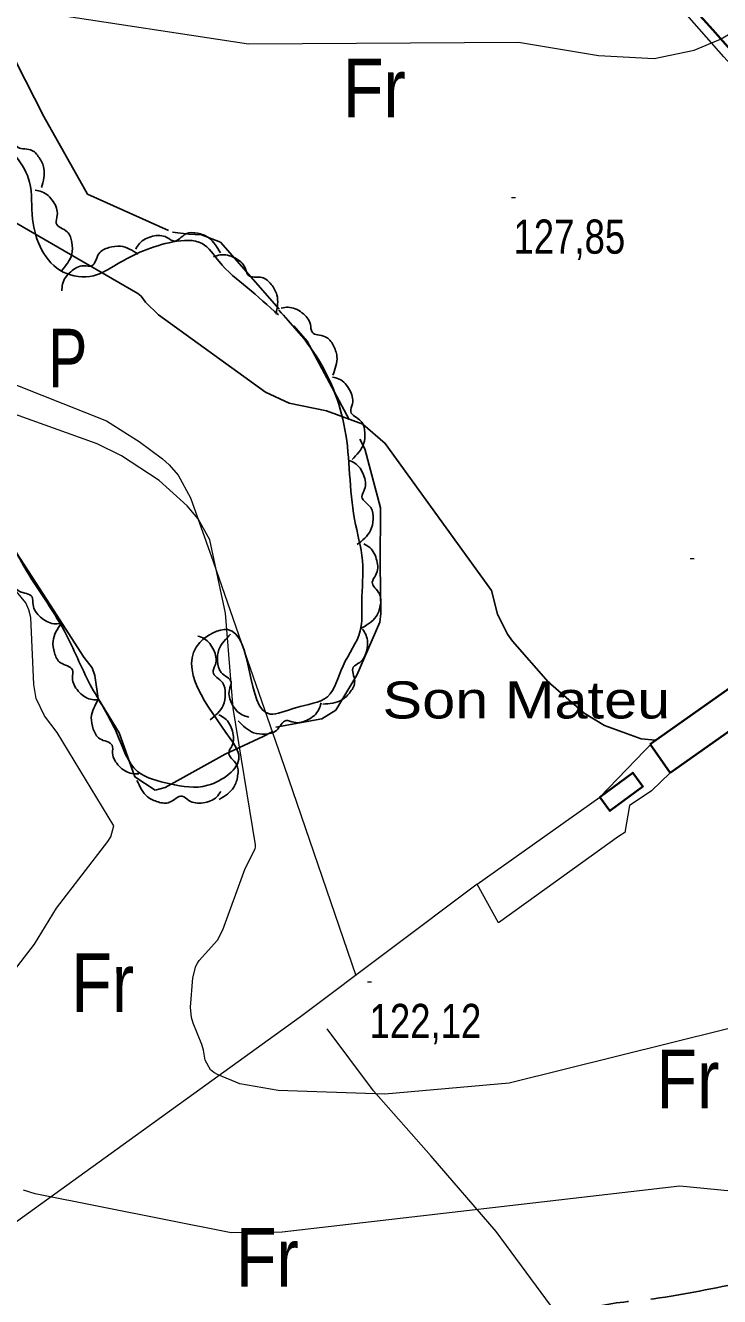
# Model space of a CAD drawing. Extents: x 483847 to 488453, y 4383581 to 4386795.
# Drawn here: x 485756 to 485933.9, y 4384534.4 to 4384859.8 of the extents above; entities that cross this region are included whole.
import ezdxf
from ezdxf.enums import TextEntityAlignment as Align

# ---------------------------------------------------------------- set-up
doc = ezdxf.new("R2010")
doc.units = 0
doc.header["$LTSCALE"] = 3.8
doc.linetypes.add('LONG_DASHED', pattern=[7.5, 6, -1.5])
for name, color, linetype, lineweight in [('25', 7, 'LONG_DASHED', 25), ('27', 7, 'Continuous', 25), ('38', 7, 'Continuous', 25), ('47', 7, 'Continuous', 35), ('51', 7, 'Continuous', 13), ('6', 7, 'Continuous', 35), ('7', 7, 'Continuous', 13), ('8', 7, 'Continuous', 25), ('9', 7, 'Continuous', 13)]:
    doc.layers.add(name, color=color, linetype=linetype, lineweight=lineweight)
doc.layers.add('31', color=7, linetype='Continuous')
doc.layers.add('5', color=7, linetype='Continuous')

msp = doc.modelspace()

# ---------------------------------------------------------------- linework, layer by layer
at = {"layer": '25'}
for points in [[(485737.43, 4384861.64), (485748.45, 4384855.7), (485753.63, 4384850.45), (485760.78, 4384836.54), (485771.9, 4384816.65), (485793.75, 4384806.88), (485797.87, 4384806.37), (485801.17, 4384806.25), (485806.02, 4384804.3), (485828.24, 4384779), (485843, 4384751.47), (485846.99, 4384736.33), (485846.93, 4384721.85), (485847.05, 4384709.24), (485846.79, 4384707.07), (485840.9, 4384693.5), (485835.52, 4384684.5), (485831.96, 4384682.3), (485820.15, 4384680.22)], [(485819.28, 4384679), (485816.96, 4384677.78), (485807.22, 4384673.27), (485791.86, 4384664.71), (485789.3, 4384664.07), (485784.02, 4384667.45), (485780.06, 4384678.76), (485774.63, 4384687.55), (485773.81, 4384693.41), (485773.09, 4384695.37), (485770.95, 4384698.1), (485762.37, 4384711.51), (485748.86, 4384732.34), (485727.51, 4384745.77), (485724.07, 4384746.42), (485717.84, 4384746.21), (485716.04, 4384745.94), (485697.39, 4384732.85), (485694.47, 4384728.16), (485689.48, 4384725.68), (485678.02, 4384742.58), (485665.24, 4384761.82), (485657.95, 4384774.45)]]:
    msp.add_lwpolyline(points, dxfattribs=at)
at = {"layer": '27'}
for points in [[(485820.93, 4384786.91), (485829.93, 4384776.12), (485837.9, 4384756.42), (485840.34, 4384733.43), (485842.37, 4384722.82), (485842.22, 4384712.24), (485841.81, 4384704.82), (485837.4, 4384695.88), (485833.39, 4384687.98), (485825.25, 4384685.17), (485818.69, 4384683.54), (485807.82, 4384705.15), (485800.72, 4384701.88), (485808.47, 4384677.31), (485810.73, 4384672.55), (485802.75, 4384665.31), (485793.07, 4384665.67), (485784.72, 4384668.87), (485779.53, 4384678.4), (485772.65, 4384691.03), (485766.02, 4384704.78), (485755.6, 4384721.43), (485746.57, 4384734.84), (485744.49, 4384736.3), (485736.37, 4384740.47), (485729.51, 4384748.52), (485725.04, 4384751.21), (485714.1, 4384746.79), (485702, 4384740.29), (485696.24, 4384736.32), (485692.16, 4384734.72), (485687.22, 4384735.4), (485671.47, 4384756.41), (485668.54, 4384767.03), (485665.8, 4384774.95), (485670.52, 4384784.41), (485677.36, 4384795.72), (485684.82, 4384813.84), (485690.85, 4384831.69), (485692.85, 4384845.62), (485697.04, 4384854.64), (485705.14, 4384864.95), (485713.55, 4384865.58), (485722.78, 4384860.5), (485736.67, 4384840.26), (485747.95, 4384831.55), (485757.09, 4384819.71), (485757.85, 4384810.25), (485765.69, 4384796.7), (485773.48, 4384795.76), (485779.37, 4384798.61), (485793.86, 4384804.4), (485801.29, 4384804), (485805.65, 4384799.36), (485812.83, 4384792.73), (485820.83, 4384785.71)], [(485745.45, 4384834.26), (485747.18, 4384834.64), (485750.82, 4384833.56), (485753.24, 4384830.77), (485753.86, 4384828.81), (485757.32, 4384827.97), (485759.55, 4384825.99), (485760.77, 4384823.23), (485760.16, 4384818.3)], [(485758.53, 4384817.64), (485760.26, 4384817.26), (485763.12, 4384814.76), (485764.17, 4384811.22), (485763.92, 4384809.18), (485766.71, 4384806.99), (485767.92, 4384804.26), (485767.88, 4384801.23), (485765.28, 4384797.01)], [(485784.29, 4384802.55), (485785.26, 4384804.04), (485788.6, 4384805.84), (485792.28, 4384805.56), (485794.1, 4384804.61), (485797.14, 4384806.45), (485800.12, 4384806.62), (485802.94, 4384805.51), (485805.97, 4384801.59)], [(485765.39, 4384791.85), (485765.53, 4384793.62), (485767.62, 4384796.78), (485770.99, 4384798.29), (485773.05, 4384798.32), (485774.86, 4384801.38), (485777.4, 4384802.94), (485780.4, 4384803.3), (485784.93, 4384801.28)], [(485804.25, 4384800.57), (485805.94, 4384801.09), (485809.66, 4384800.33), (485812.31, 4384797.76), (485813.09, 4384795.86), (485816.61, 4384795.32), (485819, 4384793.54), (485820.45, 4384790.88), (485820.26, 4384785.93)], [(485821.58, 4384787.48), (485823.34, 4384787.69), (485826.87, 4384786.29), (485829.03, 4384783.3), (485829.47, 4384781.29), (485832.83, 4384780.14), (485834.88, 4384777.97), (485835.84, 4384775.1), (485834.79, 4384770.26)], [(485834.71, 4384769.81), (485836.41, 4384769.29), (485839.05, 4384766.57), (485839.8, 4384762.95), (485839.38, 4384760.94), (485841.99, 4384758.52), (485842.97, 4384755.7), (485842.68, 4384752.69), (485839.73, 4384748.7)], [(485838.8, 4384748.53), (485840.41, 4384747.79), (485842.67, 4384744.75), (485842.94, 4384741.07), (485842.26, 4384739.13), (485844.52, 4384736.38), (485845.12, 4384733.46), (485844.44, 4384730.51), (485840.99, 4384726.94)], [(485765.07, 4384706.73), (485763.29, 4384706.66), (485759.9, 4384708.35), (485757.99, 4384711.51), (485757.72, 4384713.55), (485754.46, 4384714.97), (485752.6, 4384717.3), (485751.87, 4384720.24), (485753.32, 4384724.98)], [(485842.73, 4384727.11), (485844.23, 4384726.16), (485846.06, 4384722.83), (485845.82, 4384719.15), (485844.89, 4384717.32), (485846.75, 4384714.29), (485846.95, 4384711.31), (485845.87, 4384708.49), (485841.97, 4384705.42)], [(485774.49, 4384687.17), (485772.72, 4384687.33), (485769.57, 4384689.43), (485768.08, 4384692.81), (485768.06, 4384694.86), (485765.01, 4384696.69), (485763.46, 4384699.24), (485763.11, 4384702.24), (485765.15, 4384706.76)], [(485800.23, 4384703.49), (485801.87, 4384702.83), (485804.27, 4384699.89), (485804.7, 4384696.22), (485804.11, 4384694.25), (485806.49, 4384691.61), (485807.22, 4384688.72), (485806.67, 4384685.75), (485803.39, 4384682.03)], [(485813.23, 4384682.78), (485811.55, 4384683.33), (485808.96, 4384686.1), (485808.28, 4384689.73), (485808.73, 4384691.73), (485806.17, 4384694.2), (485805.24, 4384697.04), (485805.59, 4384700.04), (485808.61, 4384703.98)], [(485842.36, 4384705.27), (485843.29, 4384703.76), (485843.49, 4384699.98), (485841.67, 4384696.76), (485840.03, 4384695.52), (485840.39, 4384691.99), (485839.27, 4384689.22), (485837.07, 4384687.15), (485832.22, 4384686.09)], [(485785.07, 4384668.22), (485783.3, 4384668.28), (485780.04, 4384670.21), (485778.37, 4384673.51), (485778.24, 4384675.56), (485775.1, 4384677.21), (485773.41, 4384679.68), (485772.91, 4384682.66), (485774.71, 4384687.28)], [(485831.76, 4384686.37), (485831.21, 4384684.69), (485828.43, 4384682.1), (485824.8, 4384681.43), (485822.8, 4384681.88), (485820.33, 4384679.33), (485817.49, 4384678.41), (485814.48, 4384678.76), (485810.55, 4384681.79)], [(485805.59, 4384683.33), (485807.12, 4384682.43), (485809.07, 4384679.18), (485808.97, 4384675.48), (485808.12, 4384673.62), (485810.09, 4384670.67), (485810.4, 4384667.7), (485809.43, 4384664.84), (485805.66, 4384661.63)], [(485806.13, 4384663.72), (485805.04, 4384662.32), (485801.55, 4384660.82), (485797.91, 4384661.41), (485796.18, 4384662.52), (485792.98, 4384660.95), (485790, 4384661.04), (485787.29, 4384662.38), (485784.61, 4384666.55)], [(485586.07, 4384404.96), (485597.78, 4384411.17), (485606.35, 4384417.2), (485622.8, 4384434.3), (485638.04, 4384445.26), (485644.5, 4384445.62), (485658.99, 4384445.86), (485668.07, 4384446.18), (485677.83, 4384446.56), (485685.78, 4384446.52), (485686.16, 4384446.52), (485695.75, 4384445.63), (485705.07, 4384446.85), (485720.26, 4384453.83), (485731.69, 4384460.95), (485744.83, 4384466.76), (485753.85, 4384468.21), (485762.1, 4384467.94), (485771.46, 4384466.38), (485779.77, 4384465.21), (485792.44, 4384459.25), (485803.25, 4384459.25), (485830.42, 4384465.39), (485855.97, 4384473.28), (485881.92, 4384482.28), (485908.3, 4384490.54), (485915.32, 4384493.44), (485922.33, 4384495.59), (485931.48, 4384495.68), (485950.13, 4384498.57), (485982.66, 4384501.4), (486018.63, 4384502.69), (486042.78, 4384507.44), (486070.69, 4384512.67), (486104.24, 4384513.09), (486123.28, 4384517.17), (486134.56, 4384518.36), (486141.25, 4384519.31), (486150.43, 4384521.51), (486171.2, 4384525.11), (486181.12, 4384526.7), (486198.83, 4384526.52), (486209.89, 4384528.39), (486216.24, 4384532.2), (486231.76, 4384541.73), (486248.98, 4384549.44), (486261.04, 4384553.17), (486271.06, 4384556.25), (486282.21, 4384558.87), (486287.69, 4384558.94), (486300.96, 4384558.6), (486310.55, 4384557.18), (486316.3, 4384555.23), (486321.69, 4384554.32), (486328.92, 4384556.7), (486335.23, 4384562.38), (486343.66, 4384568.94), (486364.13, 4384578.33), (486366, 4384578), (486368.6, 4384576.09), (486369.79, 4384575.39), (486372.24, 4384574.08), (486374.23, 4384571.43), (486375.15, 4384567.21), (486374.25, 4384561.97), (486372.4, 4384559.07), (486370.63, 4384555.87), (486352.9, 4384543.97), (486339.38, 4384532.31), (486332.19, 4384527.76), (486317.97, 4384520.39), (486311.22, 4384515.38), (486308.88, 4384513.84), (486298.76, 4384488.69), (486287.54, 4384464.54), (486285.75, 4384455.41), (486283.18, 4384443.07), (486279.57, 4384432.24), (486279.26, 4384426.39), (486278.79, 4384419.5), (486290, 4384406.28), (486334.09, 4384403.62), (486358.16, 4384397.5), (486380.73, 4384396.58), (486398.89, 4384396.32), (486406.69, 4384396.05), (486425.56, 4384393.46), (486433.95, 4384392.44), (486444.35, 4384390.71), (486451.38, 4384388.51), (486459.96, 4384385.16)]]:
    msp.add_spline(points, degree=3, dxfattribs=at)
at = {"layer": '38', "linetype": 'LONG_DASHED'}
msp.add_spline([(485450.32, 4384320.61), (485462.4, 4384320.51), (485473.43, 4384320.88), (485482.62, 4384323.37), (485490, 4384324.99), (485501.85, 4384330.15), (485516.14, 4384337.75), (485524.23, 4384341.46), (485529.61, 4384345.21), (485577.96, 4384368.38), (485586, 4384374.12), (485596.57, 4384383.8), (485611.96, 4384394.76), (485621.26, 4384405.35), (485631.35, 4384418.34), (485634.75, 4384424.97), (485637, 4384429.97), (485638.56, 4384434.37), (485640.35, 4384438.77), (485643.85, 4384441.95), (485651.49, 4384446.42), (485654.54, 4384449.45), (485656.6, 4384451.89), (485673.07, 4384454.44), (485675.46, 4384454.03), (485679.49, 4384452.62), (485718.1, 4384455.44), (485729.3, 4384461.58), (485760.12, 4384476.15), (485767.32, 4384476.05), (485770.98, 4384475.09), (485773.52, 4384473.93), (485779.62, 4384470.09), (485800.09, 4384479.48), (485803.29, 4384483.18), (485810.72, 4384488.63), (485821.25, 4384495.76), (485840.3, 4384505.47), (485862.7, 4384518.73), (485872.14, 4384522.34), (485887.66, 4384526.92), (485901.83, 4384531.75), (485917.02, 4384533.86), (485940.42, 4384538.02), (485963.89, 4384541.96), (485980.94, 4384549), (485983.45, 4384550.99), (485984.28, 4384556.38), (485984.82, 4384562.6), (485988.91, 4384576.12), (485990.86, 4384596.58), (485991.2, 4384615.56), (485990.27, 4384628.78), (485985.71, 4384640.7), (485973.12, 4384647.03), (485967.85, 4384650.79), (485962.31, 4384652.22), (485945.83, 4384664.31), (485943.49, 4384668.84), (485940.51, 4384675.64), (485940.42, 4384675.76)], degree=3, dxfattribs=at)
at = {"layer": '47'}
for points in [[(485916.06, 4384675.84), (485941.6, 4384693.82), (485946.75, 4384686.51), (485921.21, 4384668.53)], [(485903.18, 4384662.29), (485911.63, 4384668.53), (485914.25, 4384664.99), (485905.8, 4384658.75)]]:
    msp.add_lwpolyline(points, close=True, dxfattribs=at)
at = {"layer": '51'}
for points in [[(485943.4, 4384693.68), (485995.22, 4384733.68), (486026.99, 4384756.87), (486028.59, 4384758.12), (486029.05, 4384758.71), (486029.82, 4384760.28), (486020.31, 4384767.02), (486005.23, 4384777.66), (485993.83, 4384788.63), (485987.41, 4384795.93), (485978.38, 4384804.91), (485958.28, 4384826.36), (485935.01, 4384851.75), (485913.45, 4384876.3), (485888.7, 4384903.29), (485871.64, 4384922.45), (485863.33, 4384934.27), (485854.19, 4384945.58), (485850, 4384951.95), (485847.79, 4384954.83), (485847.28, 4384955.66), (485846.47, 4384956.72)], [(485748.94, 4384769.63), (485776.77, 4384758.57), (485782.2, 4384755.2), (485785.18, 4384753.28), (485791.12, 4384748.91), (485792.82, 4384747.31), (485795.18, 4384744.73), (485798.33, 4384738.91), (485804.17, 4384722.61), (485822.33, 4384670.2), (485840.66, 4384616.62)], [(485921.21, 4384668.53), (485916.41, 4384663.9), (485915.8, 4384663.46), (485910.8, 4384660.16), (485909.58, 4384653.2), (485907.99, 4384652.17), (485877.21, 4384630.1), (485871.8, 4384640.01), (485903.18, 4384662.29), (485916.98, 4384676.49)], [(485871.8, 4384640.01), (485826.51, 4384605.99), (485743.79, 4384546.47), (485696.68, 4384510.22), (485687.56, 4384502.33)], [(485891.98, 4384530.24), (485876.67, 4384551.09), (485859.99, 4384570.32), (485845.22, 4384587.04), (485833.37, 4384602.96)]]:
    msp.add_lwpolyline(points, dxfattribs=at)
at = {"layer": '6'}
msp.add_lwpolyline([(485848.5, 4384958.28), (485858.98, 4384943.82), (485873.22, 4384924.97), (485884.69, 4384911.41), (485895.78, 4384898.93), (485914.77, 4384877.86), (485932.13, 4384858.72), (485950.08, 4384838.41), (485969.52, 4384818.02), (485987.78, 4384798.02), (486000.62, 4384784.64), (486017.02, 4384770.37), (486029.23, 4384762), (486031.51, 4384760.15)], dxfattribs=at)
at = {"layer": '7'}
for p, q in [((485880.57, 4384815.76), (485881.57, 4384815.76)), ((485926.37, 4384723.33), (485927.37, 4384723.33)), ((485843.7, 4384614.96), (485844.7, 4384614.96))]:
    msp.add_line(p, q, dxfattribs=at)
at = {"layer": '8'}
msp.add_lwpolyline([(485917.44, 4384676.81), (485913.81, 4384677.18), (485904.37, 4384680.6), (485899.2, 4384683.76), (485889.94, 4384691.78), (485880.82, 4384702.19), (485879.54, 4384703.99), (485876.99, 4384709.15), (485875.46, 4384715.17), (485848.23, 4384752.81), (485842.49, 4384757.71), (485833.19, 4384761.15), (485823.64, 4384763.11), (485817.54, 4384765.9), (485790.13, 4384785.71), (485786.81, 4384789.01), (485785.67, 4384790.51), (485784.81, 4384791.21), (485731.37, 4384822.13)], dxfattribs=at)
at = {"layer": '9'}
for points in [[(485761.52, 4384862.98), (485813.17, 4384855.14), (485882.37, 4384855.57), (485902.89, 4384852.16), (485917.14, 4384851.35), (485927.33, 4384853.51), (485934.1, 4384856.35), (485973.75, 4384879.49)], [(485976.57, 4384613.06), (485879.97, 4384589.03), (485848.09, 4384586.2), (485820.81, 4384587.15), (485810.95, 4384588.9), (485805.41, 4384591.15), (485804.34, 4384591.8), (485803.48, 4384592.45), (485802.04, 4384594.91), (485801.66, 4384597.49), (485801.24, 4384598.96), (485798.97, 4384604.42), (485798.59, 4384605.89), (485798.34, 4384608.49), (485798.89, 4384615.98), (485799.72, 4384619.01), (485800.1, 4384619.75), (485800.55, 4384620.45), (485805.27, 4384625.65), (485806.64, 4384628.29), (485812.3, 4384643.97), (485814.85, 4384649), (485814.96, 4384649.54), (485815.01, 4384650.08), (485809.27, 4384685.02), (485807.31, 4384709.36), (485803.27, 4384728.14), (485800.28, 4384733.53), (485797.46, 4384736.83), (485790.25, 4384743.36), (485780.64, 4384749.68), (485774.43, 4384752.68), (485746.47, 4384762.68)], [(485753.26, 4384617.95), (485758.37, 4384624.59), (485763.97, 4384633.84), (485777.15, 4384650.92), (485777.88, 4384652.14), (485778.71, 4384654.88), (485764.13, 4384678.84), (485760.89, 4384683.09), (485758.78, 4384687.55), (485758.16, 4384691.14), (485757.41, 4384708.25), (485756.86, 4384710.21), (485756.14, 4384711.98), (485752.15, 4384716.84)], [(485961.36, 4384558.97), (485923.67, 4384562.68), (485821.81, 4384550.94), (485808.7, 4384550.73), (485758.54, 4384560.72), (485755.54, 4384561.64)]]:
    msp.add_lwpolyline(points, dxfattribs=at)

# ---------------------------------------------------------------- texts
at = {"layer": '31'}
for s, width, p in [('Fr', 0.85, (485845.41, 4384836.28)), ('P', 0.75, (485766.87, 4384767.16)), ('Fr', 0.85, (485775.82, 4384607.25)), ('Fr', 0.85, (485925.76, 4384582.64)), ('Fr', 0.85, (485817.99, 4384536.93))]:
    msp.add_text(s, height=15, dxfattribs=dict(at, width=width)).set_placement(p, align=Align.CENTER)
at = {"layer": '5', "width": 1.2}
msp.add_text('Son Mateu', height=9.5, dxfattribs=at).set_placement((485847.51, 4384682.4))
at = {"layer": '7', "width": 0.8}
for s, p in [('127,85', (485881.07, 4384801.39)), ('122,12', (485844.2, 4384600.59))]:
    msp.add_text(s, height=8.75, dxfattribs=at).set_placement(p)

doc.saveas('drawing.dxf')
